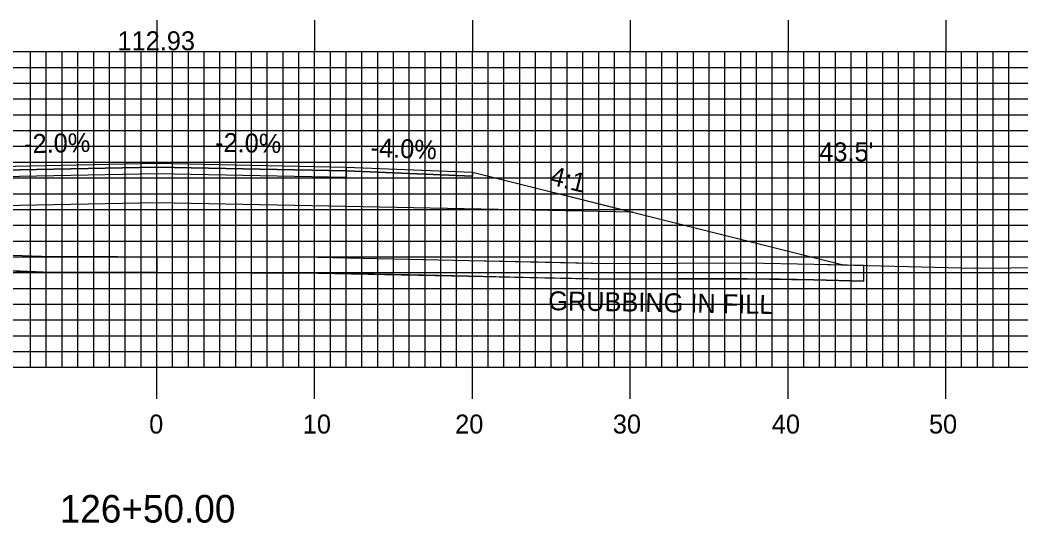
# Model space of a CAD drawing. Extents: x 1773203 to 1773546, y 442591 to 442811.
# Drawn here: x 1773360 to 1773423.4, y 442678.8 to 442710.7 of the extents above; entities that cross this region are included whole.
import ezdxf

# ---------------------------------------------------------------- set-up
doc = ezdxf.new("R2010")
doc.units = 0
for name, color, linetype in [('ANNOTATION', 7, 'Continuous'), ('D_Drainage_Culvert', 7, 'Continuous'), ('D_Roadway_Centerline', 7, 'Continuous'), ('D_Roadway_Centerline_Text', 7, 'Continuous'), ('D_Roadway_Edge_Shoulder', 7, 'Continuous'), ('D_Roadway_Edge_TW', 7, 'Continuous'), ('D_Roadway_Pavement', 7, 'Continuous'), ('D_Roadway_SlopeLines', 7, 'Continuous'), ('D_Roadway_SubGrade', 7, 'Continuous'), ('D_Text_Standard', 7, 'Continuous'), ('GRUBBING IN FILL', 7, 'Continuous'), ('H_V ANNOTATION', 7, 'Continuous'), ('MAJOR', 7, 'Continuous'), ('MINOR', 7, 'Continuous'), ('S_Roadway_Centerline', 7, 'Continuous')]:
    doc.layers.add(name, color=color, linetype=linetype)

msp = doc.modelspace()

# ---------------------------------------------------------------- linework, layer by layer
at = {"layer": 'D_Drainage_Culvert'}
msp.add_line((1773380.633, 442701.354), (1773388.632, 442701.034), dxfattribs=at)
at = {"layer": 'D_Roadway_Centerline'}
msp.add_lwpolyline([(1773329.514, 442696.626), (1773346.862, 442700.963), (1773356.633, 442701.354), (1773368.633, 442701.594), (1773380.633, 442701.354), (1773388.632, 442701.034), (1773388.632, 442701.034), (1773412.135, 442695.159)], dxfattribs=at)
at = {"layer": 'D_Roadway_Edge_Shoulder'}
msp.add_lwpolyline([(1773380.633, 442701.354), (1773388.632, 442701.034), (1773388.632, 442700.784), (1773380.633, 442701.104)], close=True, dxfattribs=at)
at = {"layer": 'D_Roadway_Edge_TW'}
msp.add_lwpolyline([(1773356.633, 442701.104), (1773356.633, 442701.354), (1773368.633, 442701.594), (1773380.633, 442701.354), (1773380.633, 442701.104), (1773368.633, 442701.344)], close=True, dxfattribs=at)
at = {"layer": 'D_Roadway_Pavement'}
msp.add_lwpolyline([(1773356.633, 442700.687), (1773356.633, 442701.104), (1773368.633, 442701.344), (1773380.633, 442701.104), (1773380.633, 442700.687), (1773368.633, 442700.927)], close=True, dxfattribs=at)
at = {"layer": 'D_Roadway_SlopeLines'}
msp.add_lwpolyline([(1773380.633, 442701.354), (1773388.632, 442701.034), (1773412.135, 442695.159)], dxfattribs=at)
at = {"layer": 'D_Roadway_SubGrade'}
msp.add_lwpolyline([(1773356.633, 442698.854), (1773336.84, 442698.458), (1773346.862, 442700.963), (1773346.862, 442700.713), (1773356.633, 442701.104), (1773368.633, 442701.344), (1773380.633, 442701.104), (1773388.632, 442700.784), (1773388.632, 442700.784), (1773388.632, 442701.034), (1773398.808, 442698.49), (1773380.633, 442698.854), (1773368.633, 442699.094)], close=True, dxfattribs=at)
at = {"layer": 'GRUBBING IN FILL'}
msp.add_line((1773413.419, 442695.127), (1773413.419, 442694.127), dxfattribs=at)
msp.add_line((1773413.419, 442695.127), (1773413.419, 442694.127), dxfattribs=at)
for points in [[(1773336.84, 442696.38), (1773338.148, 442696.348), (1773343.893, 442696.205), (1773346.807, 442696.136), (1773349.72, 442696.067), (1773353.379, 442695.962), (1773357.037, 442695.858), (1773359.487, 442695.766), (1773361.937, 442695.674), (1773366.151, 442695.682), (1773368.633, 442695.672), (1773368.633, 442694.672), (1773366.15, 442694.682), (1773364.034, 442694.678), (1773361.919, 442694.674), (1773359.462, 442694.766), (1773357.004, 442694.858), (1773353.349, 442694.963), (1773349.694, 442695.067), (1773343.869, 442695.206), (1773340.355, 442695.293), (1773336.84, 442695.38)], [(1773336.84, 442696.38), (1773338.148, 442696.348), (1773343.893, 442696.205), (1773346.807, 442696.136), (1773349.72, 442696.067), (1773353.379, 442695.962), (1773357.037, 442695.858), (1773359.487, 442695.766), (1773361.937, 442695.674), (1773366.151, 442695.682), (1773368.633, 442695.672), (1773368.633, 442694.672), (1773366.15, 442694.682), (1773364.034, 442694.678), (1773361.919, 442694.674), (1773359.462, 442694.766), (1773357.004, 442694.858), (1773353.349, 442694.963), (1773349.694, 442695.067), (1773343.869, 442695.206), (1773340.355, 442695.293), (1773336.84, 442695.38)], [(1773368.633, 442695.672), (1773372.496, 442695.657), (1773378.841, 442695.632), (1773383.62, 442695.533), (1773388.399, 442695.435), (1773392.76, 442695.342), (1773397.121, 442695.25), (1773401.585, 442695.264), (1773406.048, 442695.277), (1773410.297, 442695.204), (1773413.419, 442695.127), (1773413.419, 442694.127), (1773410.276, 442694.204), (1773408.159, 442694.241), (1773406.041, 442694.277), (1773401.576, 442694.264), (1773397.112, 442694.25), (1773392.745, 442694.342), (1773388.378, 442694.435), (1773383.603, 442694.533), (1773378.829, 442694.632), (1773372.489, 442694.657), (1773368.633, 442694.672)], [(1773368.633, 442695.672), (1773372.496, 442695.657), (1773378.841, 442695.632), (1773383.62, 442695.533), (1773388.399, 442695.435), (1773392.76, 442695.342), (1773397.121, 442695.25), (1773401.585, 442695.264), (1773406.048, 442695.277), (1773410.297, 442695.204), (1773413.419, 442695.127), (1773413.419, 442694.127), (1773410.276, 442694.204), (1773408.159, 442694.241), (1773406.041, 442694.277), (1773401.576, 442694.264), (1773397.112, 442694.25), (1773392.745, 442694.342), (1773388.378, 442694.435), (1773383.603, 442694.533), (1773378.829, 442694.632), (1773372.489, 442694.657), (1773368.633, 442694.672)]]:
    msp.add_lwpolyline(points, close=True, dxfattribs=at)
msp.add_lwpolyline([(1773336.84, 442695.38), (1773343.869, 442695.206), (1773349.694, 442695.067), (1773357.004, 442694.858), (1773361.919, 442694.674), (1773366.15, 442694.682), (1773378.829, 442694.632), (1773388.378, 442694.435), (1773397.112, 442694.25), (1773406.041, 442694.277), (1773410.276, 442694.204), (1773413.419, 442694.127)], dxfattribs=at)
msp.add_lwpolyline([(1773336.84, 442695.38), (1773343.869, 442695.206), (1773349.694, 442695.067), (1773357.004, 442694.858), (1773361.919, 442694.674), (1773366.15, 442694.682), (1773378.829, 442694.632), (1773388.378, 442694.435), (1773397.112, 442694.25), (1773406.041, 442694.277), (1773410.276, 442694.204), (1773413.419, 442694.127)], dxfattribs=at)
at = {"layer": 'MAJOR'}
for p, q in [((1773368.633, 442710.669), (1773368.633, 442708.665)), ((1773378.633, 442710.669), (1773378.633, 442708.665)), ((1773388.633, 442710.669), (1773388.633, 442708.665)), ((1773398.633, 442710.669), (1773398.633, 442708.665)), ((1773408.633, 442710.669), (1773408.633, 442708.665)), ((1773418.633, 442710.669), (1773418.633, 442708.665)), ((1773228.633, 442708.665), (1773508.633, 442708.665)), ((1773228.633, 442708.665), (1773508.633, 442708.665)), ((1773368.633, 442688.665), (1773368.633, 442708.665)), ((1773378.633, 442688.665), (1773378.633, 442708.665)), ((1773388.633, 442688.665), (1773388.633, 442708.665)), ((1773398.633, 442688.665), (1773398.633, 442708.665)), ((1773408.633, 442688.665), (1773408.633, 442708.665)), ((1773418.633, 442688.665), (1773418.633, 442708.665)), ((1773228.633, 442703.665), (1773508.633, 442703.665)), ((1773228.633, 442698.665), (1773508.633, 442698.665)), ((1773228.633, 442693.665), (1773508.633, 442693.665)), ((1773228.633, 442688.665), (1773508.633, 442688.665)), ((1773228.633, 442688.665), (1773508.633, 442688.665)), ((1773368.633, 442686.661), (1773368.633, 442688.665)), ((1773378.633, 442686.661), (1773378.633, 442688.665)), ((1773388.633, 442686.661), (1773388.633, 442688.665)), ((1773398.633, 442686.661), (1773398.633, 442688.665)), ((1773408.633, 442686.661), (1773408.633, 442688.665)), ((1773418.633, 442686.661), (1773418.633, 442688.665))]:
    msp.add_line(p, q, dxfattribs=at)
at = {"layer": 'MINOR'}
for p, q in [((1773360.633, 442688.665), (1773360.633, 442708.665)), ((1773361.633, 442688.665), (1773361.633, 442708.665)), ((1773362.633, 442688.665), (1773362.633, 442708.665)), ((1773363.633, 442688.665), (1773363.633, 442708.665)), ((1773364.633, 442688.665), (1773364.633, 442708.665)), ((1773365.633, 442688.665), (1773365.633, 442708.665)), ((1773366.633, 442688.665), (1773366.633, 442708.665)), ((1773367.633, 442688.665), (1773367.633, 442708.665)), ((1773369.633, 442688.665), (1773369.633, 442708.665)), ((1773370.633, 442688.665), (1773370.633, 442708.665)), ((1773371.633, 442688.665), (1773371.633, 442708.665)), ((1773372.633, 442688.665), (1773372.633, 442708.665)), ((1773373.633, 442688.665), (1773373.633, 442708.665)), ((1773374.633, 442688.665), (1773374.633, 442708.665)), ((1773375.633, 442688.665), (1773375.633, 442708.665)), ((1773376.633, 442688.665), (1773376.633, 442708.665)), ((1773377.633, 442688.665), (1773377.633, 442708.665)), ((1773379.633, 442688.665), (1773379.633, 442708.665)), ((1773380.633, 442688.665), (1773380.633, 442708.665)), ((1773381.633, 442688.665), (1773381.633, 442708.665)), ((1773382.633, 442688.665), (1773382.633, 442708.665)), ((1773383.633, 442688.665), (1773383.633, 442708.665)), ((1773384.633, 442688.665), (1773384.633, 442708.665)), ((1773385.633, 442688.665), (1773385.633, 442708.665)), ((1773386.633, 442688.665), (1773386.633, 442708.665)), ((1773387.633, 442688.665), (1773387.633, 442708.665)), ((1773389.633, 442688.665), (1773389.633, 442708.665)), ((1773390.633, 442688.665), (1773390.633, 442708.665)), ((1773391.633, 442688.665), (1773391.633, 442708.665)), ((1773392.633, 442688.665), (1773392.633, 442708.665)), ((1773393.633, 442688.665), (1773393.633, 442708.665)), ((1773394.633, 442688.665), (1773394.633, 442708.665)), ((1773395.633, 442688.665), (1773395.633, 442708.665)), ((1773396.633, 442688.665), (1773396.633, 442708.665)), ((1773397.633, 442688.665), (1773397.633, 442708.665)), ((1773399.633, 442688.665), (1773399.633, 442708.665)), ((1773400.633, 442688.665), (1773400.633, 442708.665)), ((1773401.633, 442688.665), (1773401.633, 442708.665)), ((1773402.633, 442688.665), (1773402.633, 442708.665)), ((1773403.633, 442688.665), (1773403.633, 442708.665)), ((1773404.633, 442688.665), (1773404.633, 442708.665)), ((1773405.633, 442688.665), (1773405.633, 442708.665)), ((1773406.633, 442688.665), (1773406.633, 442708.665)), ((1773407.633, 442688.665), (1773407.633, 442708.665)), ((1773409.633, 442688.665), (1773409.633, 442708.665)), ((1773410.633, 442688.665), (1773410.633, 442708.665)), ((1773411.633, 442688.665), (1773411.633, 442708.665)), ((1773412.633, 442688.665), (1773412.633, 442708.665)), ((1773413.633, 442688.665), (1773413.633, 442708.665)), ((1773414.633, 442688.665), (1773414.633, 442708.665)), ((1773415.633, 442688.665), (1773415.633, 442708.665)), ((1773416.633, 442688.665), (1773416.633, 442708.665)), ((1773417.633, 442688.665), (1773417.633, 442708.665)), ((1773419.633, 442688.665), (1773419.633, 442708.665)), ((1773420.633, 442688.665), (1773420.633, 442708.665)), ((1773421.633, 442688.665), (1773421.633, 442708.665)), ((1773422.633, 442688.665), (1773422.633, 442708.665)), ((1773228.633, 442707.665), (1773508.633, 442707.665)), ((1773228.633, 442706.665), (1773508.633, 442706.665)), ((1773228.633, 442705.665), (1773508.633, 442705.665)), ((1773228.633, 442704.665), (1773508.633, 442704.665)), ((1773228.633, 442702.665), (1773508.633, 442702.665)), ((1773228.633, 442701.665), (1773508.633, 442701.665)), ((1773228.633, 442700.665), (1773508.633, 442700.665)), ((1773228.633, 442699.665), (1773508.633, 442699.665)), ((1773228.633, 442697.665), (1773508.633, 442697.665)), ((1773228.633, 442696.665), (1773508.633, 442696.665)), ((1773228.633, 442695.665), (1773508.633, 442695.665)), ((1773228.633, 442694.665), (1773508.633, 442694.665)), ((1773228.633, 442692.665), (1773508.633, 442692.665)), ((1773228.633, 442691.665), (1773508.633, 442691.665)), ((1773228.633, 442690.665), (1773508.633, 442690.665)), ((1773228.633, 442689.665), (1773508.633, 442689.665))]:
    msp.add_line(p, q, dxfattribs=at)
at = {"layer": 'S_Roadway_Centerline'}
msp.add_lwpolyline([(1773306.911, 442697.34), (1773315.627, 442697.227), (1773322.548, 442696.953), (1773332.403, 442696.491), (1773343.893, 442696.205), (1773349.72, 442696.067), (1773357.037, 442695.858), (1773361.937, 442695.674), (1773366.151, 442695.682), (1773378.841, 442695.632), (1773388.399, 442695.435), (1773397.121, 442695.25), (1773406.048, 442695.277), (1773410.297, 442695.204), (1773420.484, 442694.953), (1773431.77, 442695.051)], dxfattribs=at)

# ---------------------------------------------------------------- texts
at = {"layer": 'ANNOTATION'}
for s, rotation, p in [('-2.0%', 1.14577, (1773360.239, 442702.227)), ('-2.0%', 358.85423, (1773372.319, 442702.321)), ('-4.0%', 357.70932, (1773382.165, 442702.005)), ('4:1', 345.96145, (1773393.468, 442700.259))]:
    msp.add_text(s, height=1.2, rotation=rotation, dxfattribs=at).set_placement(p)
at = {"layer": 'D_Roadway_Centerline'}
for s, p in [('C', (1773368.628, 442701.594)), ('L', (1773368.633, 442701.587))]:
    msp.add_text(s, height=0.0146, dxfattribs=at).set_placement(p)
at = {"layer": 'D_Roadway_Centerline_Text'}
msp.add_text('112.93', height=1.2, dxfattribs=at).set_placement((1773366.145, 442708.753))
at = {"layer": 'D_Text_Standard'}
msp.add_text("43.5'", height=1.2, dxfattribs=at).set_placement((1773410.613, 442701.715))
at = {"layer": 'GRUBBING IN FILL'}
msp.add_text('GRUBBING IN FILL', height=1.2, rotation=359.01917, dxfattribs=at).set_placement((1773393.431, 442692.284))
at = {"layer": 'H_V ANNOTATION'}
for s, height, p in [('0', 1.2, (1773368.151, 442684.465)), ('10', 1.2, (1773377.884, 442684.465)), ('20', 1.2, (1773387.541, 442684.465)), ('30', 1.2, (1773397.53, 442684.465)), ('40', 1.2, (1773407.605, 442684.465)), ('50', 1.2, (1773417.562, 442684.465)), ('126+50.00', 1.75, (1773362.484, 442678.821))]:
    msp.add_text(s, height=height, dxfattribs=at).set_placement(p)

doc.saveas('drawing.dxf')
